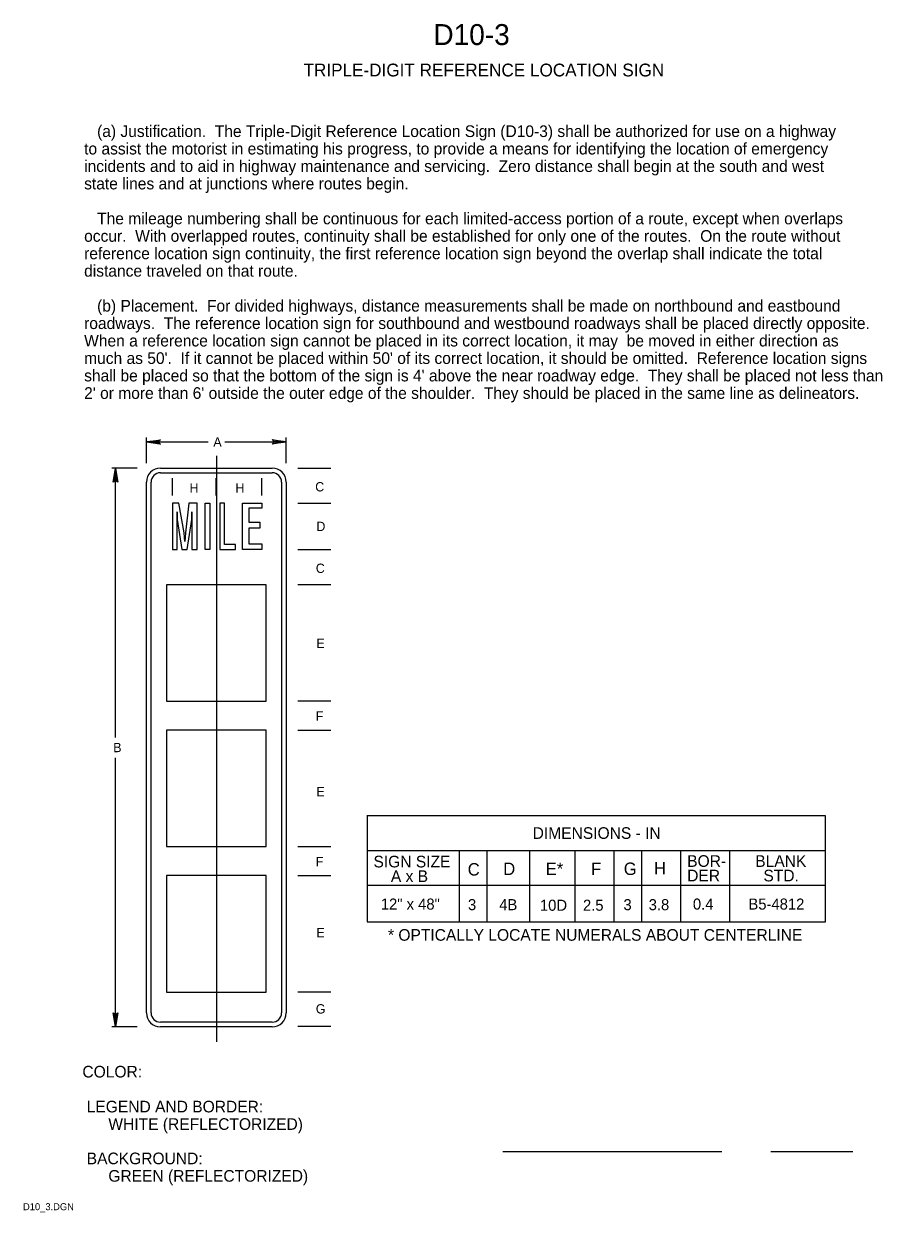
# Model space of a CAD drawing. Extents: x 0.013 to 0.197, y 0.004 to 0.259.
import ezdxf

# ---------------------------------------------------------------- set-up
doc = ezdxf.new("R2010")
doc.units = 0
for name, color, linetype in [('1', 7, 'Continuous'), ('2', 7, 'Continuous'), ('3', 7, 'Continuous')]:
    doc.layers.add(name, color=color, linetype=linetype)

# ---------------------------------------------------------------- blocks, each defined once
blk = doc.blocks.new('RARROW')
at = {"layer": '3'}
for p, q in [((-2.156, 0.285), (-2.2665, 0.384625)), ((-2.2665, 0.384625), (0, 0)), ((0, 0), (-2.2665, -0.379125)), ((-2.156, 0.285), (-2.075625, 0.12075)), ((0, 0), (-2.156, 0.285)), ((-2.14975, -0.2705), (0, 0)), ((-2.075625, 0.12075), (0, 0)), ((0, 0), (-2.074, -0.108)), ((-2.2665, -0.379125), (-2.14975, -0.2705)), ((-2.074, -0.108), (-2.14975, -0.2705))]:
    blk.add_line(p, q, dxfattribs=at)

msp = doc.modelspace()

# ---------------------------------------------------------------- linework, layer by layer
at = {"layer": '1'}
for p, q in [((0.11544, 0.01695), (0.16242, 0.01695)), ((0.17295, 0.01695), (0.19056, 0.01695))]:
    msp.add_line(p, q, dxfattribs=at)
at = {"layer": '2'}
for p, q in [((0.03891, 0.16485), (0.03891, 0.17035)), ((0.05216, 0.16935), (0.03891, 0.16935)), ((0.06891, 0.16935), (0.05572, 0.16935)), ((0.06891, 0.16485), (0.06891, 0.17035)), ((0.03692, 0.16376), (0.03142, 0.16376)), ((0.03225, 0.10588), (0.03225, 0.16374)), ((0.07138, 0.16375), (0.0785, 0.16375)), ((0.0445, 0.15788), (0.0445, 0.16162)), ((0.05387, 0.15788), (0.05387, 0.16162)), ((0.06363, 0.15788), (0.06363, 0.16162)), ((0.07138, 0.15625), (0.0785, 0.15625)), ((0.07138, 0.14625), (0.0785, 0.14625)), ((0.04321, 0.13871), (0.04321, 0.11371)), ((0.06461, 0.13871), (0.04321, 0.13871)), ((0.06461, 0.11371), (0.06461, 0.13871)), ((0.07138, 0.13875), (0.0785, 0.13875)), ((0.04321, 0.11371), (0.06461, 0.11371)), ((0.07138, 0.11375), (0.0785, 0.11375)), ((0.04322, 0.10749), (0.04322, 0.08249)), ((0.06462, 0.10749), (0.04322, 0.10749)), ((0.06462, 0.08249), (0.06462, 0.10749)), ((0.07138, 0.1075), (0.0785, 0.1075)), ((0.03225, 0.04374), (0.03225, 0.1015)), ((0.04322, 0.08249), (0.06462, 0.08249)), ((0.07138, 0.0825), (0.0785, 0.0825)), ((0.04322, 0.07624), (0.04322, 0.05124)), ((0.06462, 0.07624), (0.04322, 0.07624)), ((0.06462, 0.05124), (0.06462, 0.07624)), ((0.07138, 0.07625), (0.0785, 0.07625)), ((0.04322, 0.05124), (0.06462, 0.05124)), ((0.07138, 0.05125), (0.0785, 0.05125)), ((0.03692, 0.04376), (0.03142, 0.04376)), ((0.07138, 0.04388), (0.0785, 0.04388))]:
    msp.add_line(p, q, dxfattribs=at)
for points in [[(0.0445, 0.15625), (0.0445, 0.14625), (0.0455, 0.14625), (0.0455, 0.15263), (0.0455, 0.15438), (0.0455, 0.15275), (0.0465, 0.14625), (0.04763, 0.14625), (0.04863, 0.15275), (0.04863, 0.15438), (0.04863, 0.15263), (0.04863, 0.14625), (0.04975, 0.14625), (0.04975, 0.15625), (0.048, 0.15625), (0.04725, 0.14988), (0.04713, 0.148), (0.047, 0.14988), (0.04587, 0.15625), (0.0445, 0.15625)], [(0.0515, 0.14625), (0.0515, 0.15625), (0.0525, 0.15625), (0.0525, 0.14625), (0.0515, 0.14625)], [(0.05462, 0.15625), (0.05462, 0.14625), (0.058, 0.14625), (0.058, 0.14738), (0.05563, 0.14738), (0.05563, 0.15625), (0.05462, 0.15625)], [(0.0595, 0.14625), (0.0595, 0.15625), (0.06363, 0.15625), (0.06363, 0.15513), (0.06087, 0.15513), (0.06087, 0.15213), (0.06325, 0.15213), (0.06325, 0.15088), (0.06087, 0.15088), (0.06087, 0.1475), (0.06363, 0.1475), (0.06363, 0.14625), (0.0595, 0.14625)]]:
    msp.add_lwpolyline(points, dxfattribs=at)
at = {"layer": '3'}
for p, q in [((0.05389, 0.1664), (0.05389, 0.04055)), ((0.04189, 0.16376), (0.06589, 0.16376)), ((0.04189, 0.16276), (0.06589, 0.16276)), ((0.03889, 0.04676), (0.03889, 0.16076)), ((0.03989, 0.04676), (0.03989, 0.16076)), ((0.06789, 0.16076), (0.06789, 0.04676)), ((0.06889, 0.16076), (0.06889, 0.04676)), ((0.08625, 0.08917), (0.18466, 0.08917)), ((0.08627, 0.08919), (0.08627, 0.06629)), ((0.08627, 0.08919), (0.08627, 0.06629)), ((0.18466, 0.08917), (0.18466, 0.06627)), ((0.18466, 0.08154), (0.08625, 0.08154)), ((0.10602, 0.08144), (0.10602, 0.06629)), ((0.11199, 0.08144), (0.11199, 0.06629)), ((0.12112, 0.08154), (0.12112, 0.06629)), ((0.13089, 0.08154), (0.13089, 0.06629)), ((0.13923, 0.08154), (0.13923, 0.06629)), ((0.14521, 0.08154), (0.14521, 0.06629)), ((0.15354, 0.08154), (0.15354, 0.06629)), ((0.16406, 0.08154), (0.16406, 0.06629)), ((0.08625, 0.07417), (0.18466, 0.07417)), ((0.08625, 0.06629), (0.18466, 0.06629)), ((0.06589, 0.04476), (0.04189, 0.04476)), ((0.06589, 0.04376), (0.04189, 0.04376))]:
    msp.add_line(p, q, dxfattribs=at)
for centre, radius, start, end in [((0.04189, 0.16076), 0.003, 90, 180), ((0.06589, 0.16076), 0.003, 0, 90), ((0.04189, 0.16076), 0.002, 90, 180), ((0.06589, 0.16076), 0.002, 0, 90), ((0.04189, 0.04676), 0.003, 180, 270), ((0.04189, 0.04676), 0.002, 180, 270), ((0.06589, 0.04676), 0.003, 270, 0), ((0.06589, 0.04676), 0.002, 270, 0)]:
    msp.add_arc(centre, radius, start, end, dxfattribs=at)

# ---------------------------------------------------------------- block references
at = {"layer": '2', "xscale": 0.0013236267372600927, "yscale": 0.001309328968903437}
for p, rotation in [((0.03887, 0.16937), 180), ((0.03225, 0.16375), 90), ((0.03225, 0.04375), -90)]:
    msp.add_blockref('RARROW', p, dxfattribs=dict(at, rotation=rotation))
msp.add_blockref('RARROW', (0.06888, 0.16937), dxfattribs=at)

# ---------------------------------------------------------------- texts
at = {"layer": '1'}
for s, height, p in [('D10-3', 0.0045, (0.1005, 0.25462)), ('TRIPLE-DIGIT REFERENCE LOCATION SIGN', 0.0027503, (0.07261, 0.24788)), ('COLOR:', 0.0025, (0.02513, 0.03288)), (' LEGEND AND BORDER:', 0.0024998, (0.02513, 0.02538)), ('      WHITE (REFLECTORIZED)', 0.0024998, (0.02513, 0.02163)), (' BACKGROUND:', 0.0024998, (0.02513, 0.01425)), ('      GREEN (REFLECTORIZED)', 0.0024998, (0.02513, 0.0105)), ('D10_3.DGN', 0.0015, (0.01238, 0.00438))]:
    msp.add_text(s, height=height, dxfattribs=at).set_placement(p)
at = {"layer": '2'}
for s, height, p in [('   (a) Justification.  The Triple-Digit Reference Location Sign (D10-3) shall be authorized for use on a highway', 0.00249975, (0.0255, 0.23487)), ('to assist the motorist in estimating his progress, to provide a means for identifying the location of emergency', 0.00249975, (0.0255, 0.23112)), ('incidents and to aid in highway maintenance and servicing.  Zero distance shall begin at the south and west', 0.00249975, (0.0255, 0.22737)), ('state lines and at junctions where routes begin.', 0.0024998, (0.0255, 0.22362)), ('   The mileage numbering shall be continuous for each limited-access portion of a route, except when overlaps', 0.00249975, (0.0255, 0.21612)), ('occur.  With overlapped routes, continuity shall be established for only one of the routes.  On the route without', 0.00249975, (0.0255, 0.21237)), ('reference location sign continuity, the first reference location sign beyond the overlap shall indicate the total ', 0.00249975, (0.0255, 0.20863)), ('distance traveled on that route.', 0.0024998, (0.0255, 0.20488)), ('   (b) Placement.  For divided highways, distance measurements shall be made on northbound and eastbound', 0.00249975, (0.0255, 0.19738)), ('roadways.  The reference location sign for southbound and westbound roadways shall be placed directly opposite.  ', 0.00249975, (0.0255, 0.19363)), ('When a reference location sign cannot be placed in its correct location, it may  be moved in either direction as ', 0.00249975, (0.0255, 0.18988)), ("much as 50'.  If it cannot be placed within 50' of its correct location, it should be omitted.  Reference location signs", 0.00249975, (0.0255, 0.18613)), ("shall be placed so that the bottom of the sign is 4' above the near roadway edge.  They shall be placed not less than ", 0.00249975, (0.0255, 0.18238)), ("2' or more than 6' outside the outer edge of the shoulder.  They should be placed in the same line as delineators. ", 0.00249975, (0.0255, 0.17863)), ('A', 0.002, (0.05325, 0.16837)), ('H', 0.002, (0.04813, 0.1585)), ('H', 0.002, (0.058, 0.1585)), ('C', 0.002, (0.07512, 0.15875)), ('D', 0.002, (0.07537, 0.15025)), ('C', 0.002, (0.07525, 0.14125)), ('E', 0.002, (0.07537, 0.12513)), ('F', 0.002, (0.07525, 0.1095)), ('B', 0.002, (0.03175, 0.10275)), ('E', 0.002, (0.07537, 0.09325)), ('F', 0.002, (0.07525, 0.07825)), ('E', 0.002, (0.07537, 0.063)), ('G', 0.002, (0.07525, 0.04662))]:
    msp.add_text(s, height=height, dxfattribs=at).set_placement(p)
at = {"layer": '3'}
for s, height, p in [('DIMENSIONS - IN', 0.0024998, (0.12182, 0.08413)), ('SIGN SIZE', 0.0025, (0.08763, 0.078)), ('H', 0.00267, (0.14788, 0.0765)), ('H', 0.00267, (0.14788, 0.0765)), ('BOR-', 0.0025, (0.155, 0.07812)), ('BLANK', 0.0025, (0.16962, 0.07812)), ('A x B', 0.0025, (0.09137, 0.07487)), ('C', 0.00267, (0.10787, 0.07625)), ('D', 0.00267, (0.1155, 0.07637)), ('E*', 0.002672, (0.12462, 0.07637)), ('F', 0.00267, (0.13437, 0.07637)), ('G', 0.00267, (0.14138, 0.07637)), ('DER', 0.0025, (0.155, 0.075)), ('STD.', 0.0025, (0.17137, 0.075)), ('12" x 48"', 0.002375, (0.08921, 0.06894)), ('3', 0.00238, (0.10793, 0.06881)), ('4B', 0.002375, (0.11464, 0.06881)), ('10D', 0.002375, (0.12338, 0.06869)), ('2.5', 0.002375, (0.13262, 0.06869)), ('3', 0.00238, (0.14131, 0.06881)), ('3.8', 0.002375, (0.14673, 0.06881)), ('0.4', 0.002375, (0.15623, 0.06894)), ('B5-4812', 0.002375, (0.16815, 0.06894)), ('* OPTICALLY LOCATE NUMERALS ABOUT CENTERLINE', 0.0024998, (0.09075, 0.06225))]:
    msp.add_text(s, height=height, dxfattribs=at).set_placement(p)

doc.saveas('drawing.dxf')
